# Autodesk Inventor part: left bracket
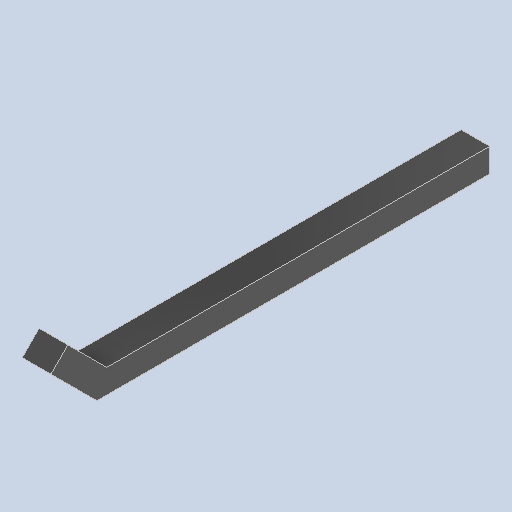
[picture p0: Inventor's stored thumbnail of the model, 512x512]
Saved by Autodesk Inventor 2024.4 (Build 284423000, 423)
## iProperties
Created: 2025-04
Part Number: left bracket
Material: Generic
Document SubType Name: Modeling
Designer: AdminForWorker
Density: 1 g/cm^3
Appearance: Default
Title: left bracket v1
Author: AdminForWorker
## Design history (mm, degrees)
feature "Body5"
body "Solid1"
